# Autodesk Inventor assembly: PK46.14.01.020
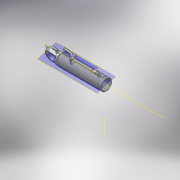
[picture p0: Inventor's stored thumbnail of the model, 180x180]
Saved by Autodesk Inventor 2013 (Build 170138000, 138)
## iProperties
Shininess: 64.0
Length Units: 11269
Angle Units: 11279
Time Units: 11290
Mass Units: 11283
Length Display Precision: 3
Angle Display Precision: 2
Compacted: True
Created: 2004-11
Part Number: PK46.14.01.020
Document SubType Name: Assembly
Designer: ELarisa
Manufacturer: Standard
Standards Organization: Custom
Density: 0.0
Volumn: 0.0
Area: 0.0
PropertySet Name: Model Information
Control State: 0
Master: False
Checked Out: False
Checked Out Date: 2008-10-15
Last Check In Date: 2008-10-15
Author: ELarisa
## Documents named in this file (9)
- C:\Product Design Suite 2013\Data\Assemblies\PK46.14.01.020.iam
- C:\Product Design Suite 2013\Data\Parts\PK46.14.01.002.ipt
- C:\Product Design Suite 2013\Data\Parts\PK46.14.01.015.ipt
- C:\Product Design Suite 2013\Data\Parts\PK46.14.01.007.ipt
- C:\Product Design Suite 2013\Data\Parts\D395B-43-192-2.ipt
- C:\Product Design Suite 2013\Data\Parts\PK46.14.01.016.ipt
- C:\Product Design Suite 2013\Data\Parts\10.65G.019.ipt
- C:\Product Design Suite 2013\Data\Assemblies\PK46.14.01.040.iam
- C:\Product Design Suite 2013\Data\Parts\M10-6gx25.58.019(S16).ipt
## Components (11 placed, 8 different names)
1. PK46.14.01.002:1 — Insert:1, Angle:1, Insert:2, Angle:3, Insert:15, Mate:3
2. PK46.14.01.007:1 — Insert:1, Angle:1, Insert:6, Angle:9
3. D395B-43-192-2:1 — Insert:2, Angle:3, Insert:17, Angle:8, Angle:10
4. D395B-43-192-2:2 — Insert:6, Angle:10
5. PK46.14.01.040:1 [sub-assembly] — Insert:17
6. PK46.14.01.015:1 — Insert:15, Insert:16, Mate:1
7. PK46.14.01.016:1 — Insert:11, Insert:12, Insert:16, Mate:1, Angle:8
8. 10.65G.019:1 — Insert:11, Insert:13
9. 10.65G.019:2 — Insert:12, Insert:14
10. M10-6gx25.58.019(S16):1 — Insert:13
11. M10-6gx25.58.019(S16):2 — Insert:14
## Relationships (17: Insert 10, Angle 5, Mate 2)
- Insert:1: PK46.14.01.002:1 ↔ PK46.14.01.007:1
- Angle:1: PK46.14.01.002:1 ↔ PK46.14.01.007:1
- Insert:2: PK46.14.01.002:1 ↔ D395B-43-192-2:1
- Angle:3: PK46.14.01.002:1 ↔ D395B-43-192-2:1
- Insert:6: PK46.14.01.007:1 ↔ D395B-43-192-2:2
- Insert:11: PK46.14.01.016:1 ↔ 10.65G.019:1
- Insert:12: PK46.14.01.016:1 ↔ 10.65G.019:2
- Insert:13: 10.65G.019:1 ↔ M10-6gx25.58.019(S16):1
- Insert:14: 10.65G.019:2 ↔ M10-6gx25.58.019(S16):2
- Insert:15: PK46.14.01.002:1 ↔ PK46.14.01.015:1
- Insert:16: PK46.14.01.015:1 ↔ PK46.14.01.016:1
- Mate:1: PK46.14.01.015:1 ↔ PK46.14.01.016:1
- Insert:17: D395B-43-192-2:1 ↔ PK46.14.01.040:1
- Angle:8: D395B-43-192-2:1 ↔ PK46.14.01.016:1
- Mate:3: PK46.14.01.002:1
- Angle:9: PK46.14.01.007:1
- Angle:10: D395B-43-192-2:1 ↔ D395B-43-192-2:2
